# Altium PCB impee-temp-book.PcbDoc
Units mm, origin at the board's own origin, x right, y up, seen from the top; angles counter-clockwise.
Board outline 63.5 x 86.36 mm, 2 copper layers (Top Layer, Bottom Layer); 35 components, 21 nets, 124 pads, 134 vias.
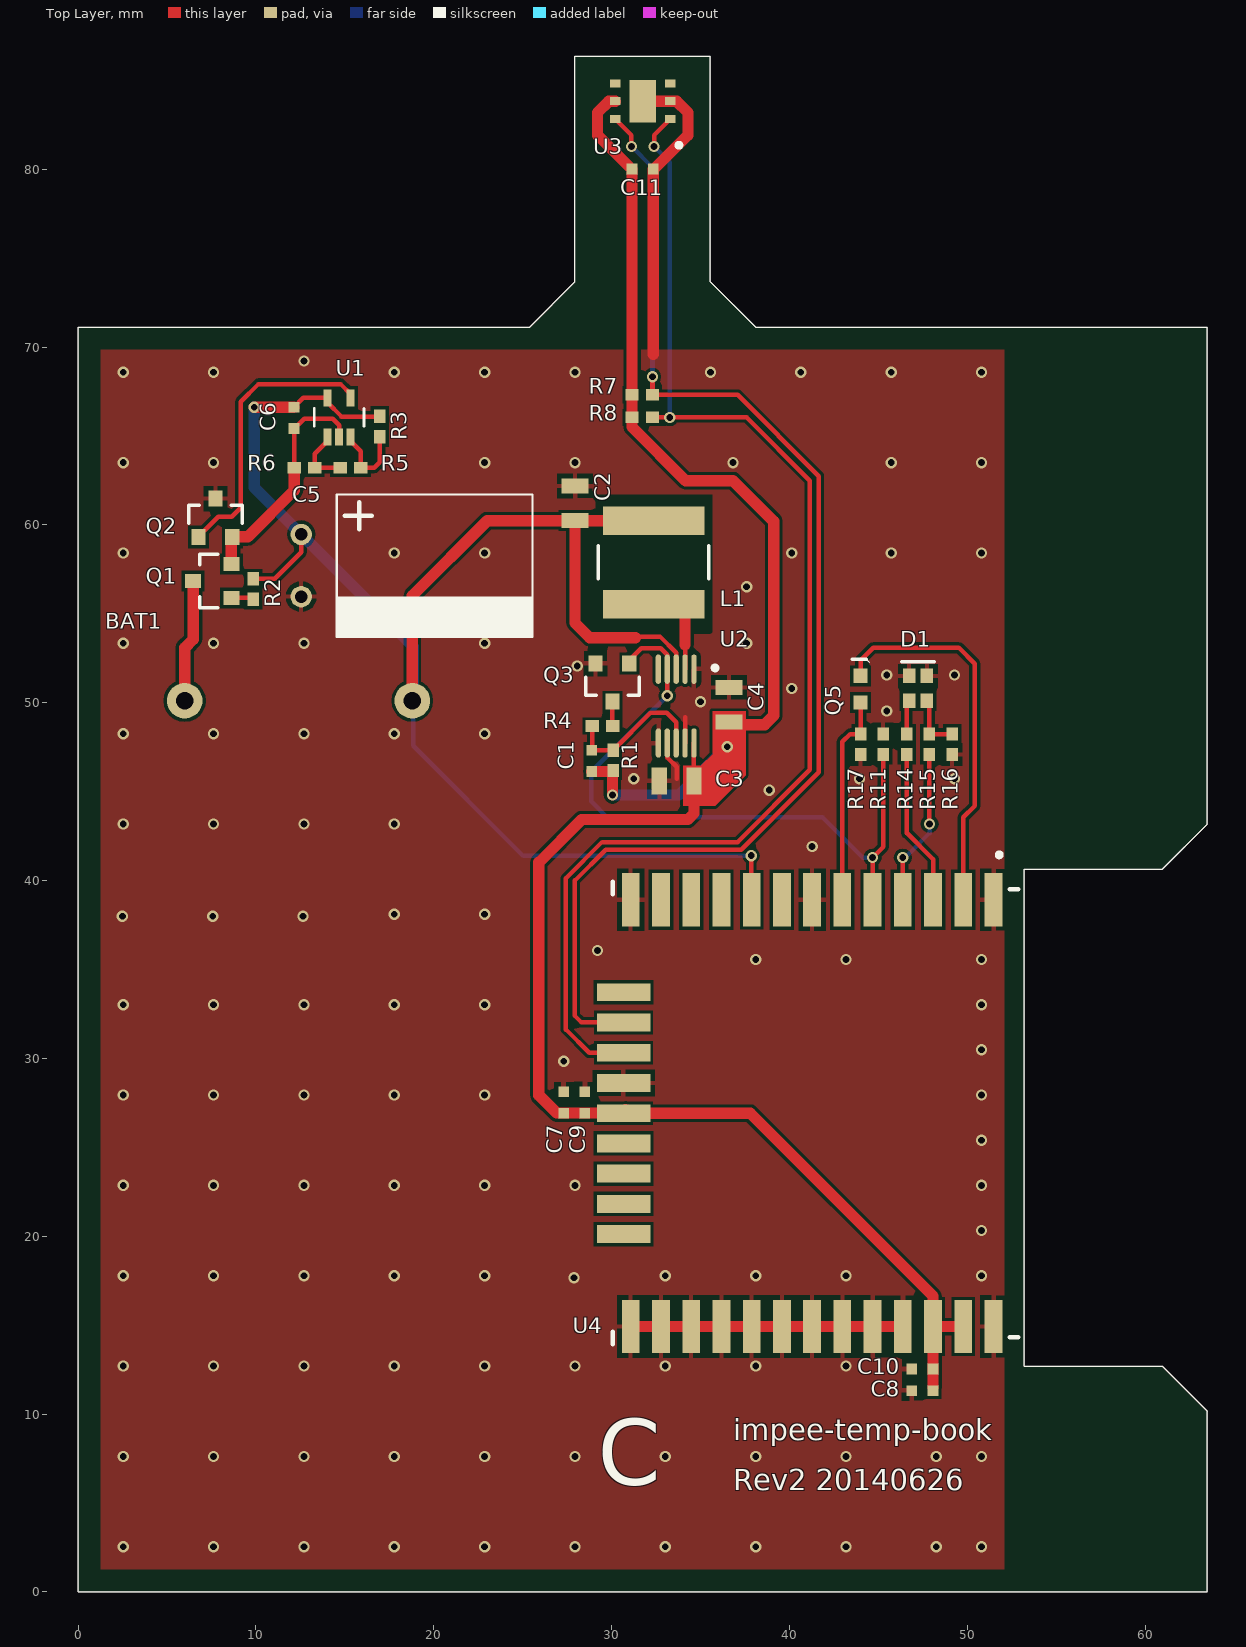
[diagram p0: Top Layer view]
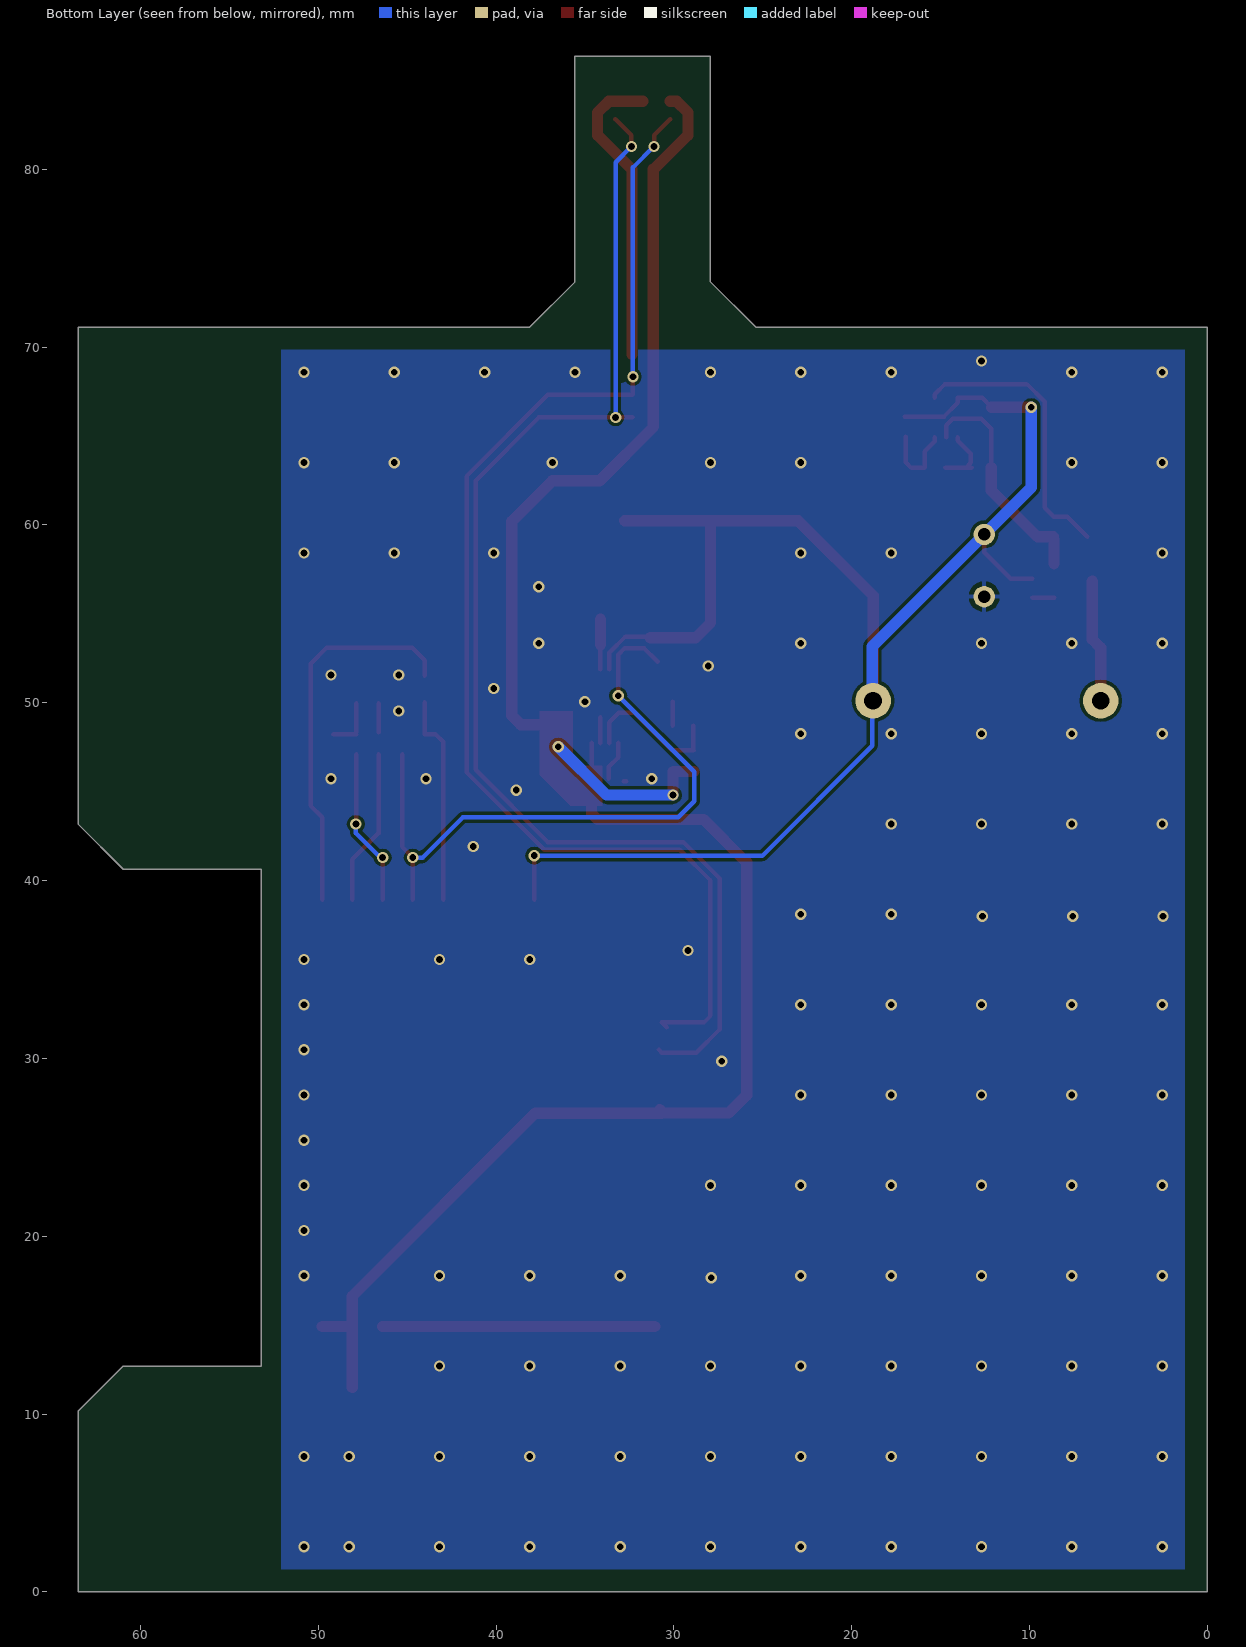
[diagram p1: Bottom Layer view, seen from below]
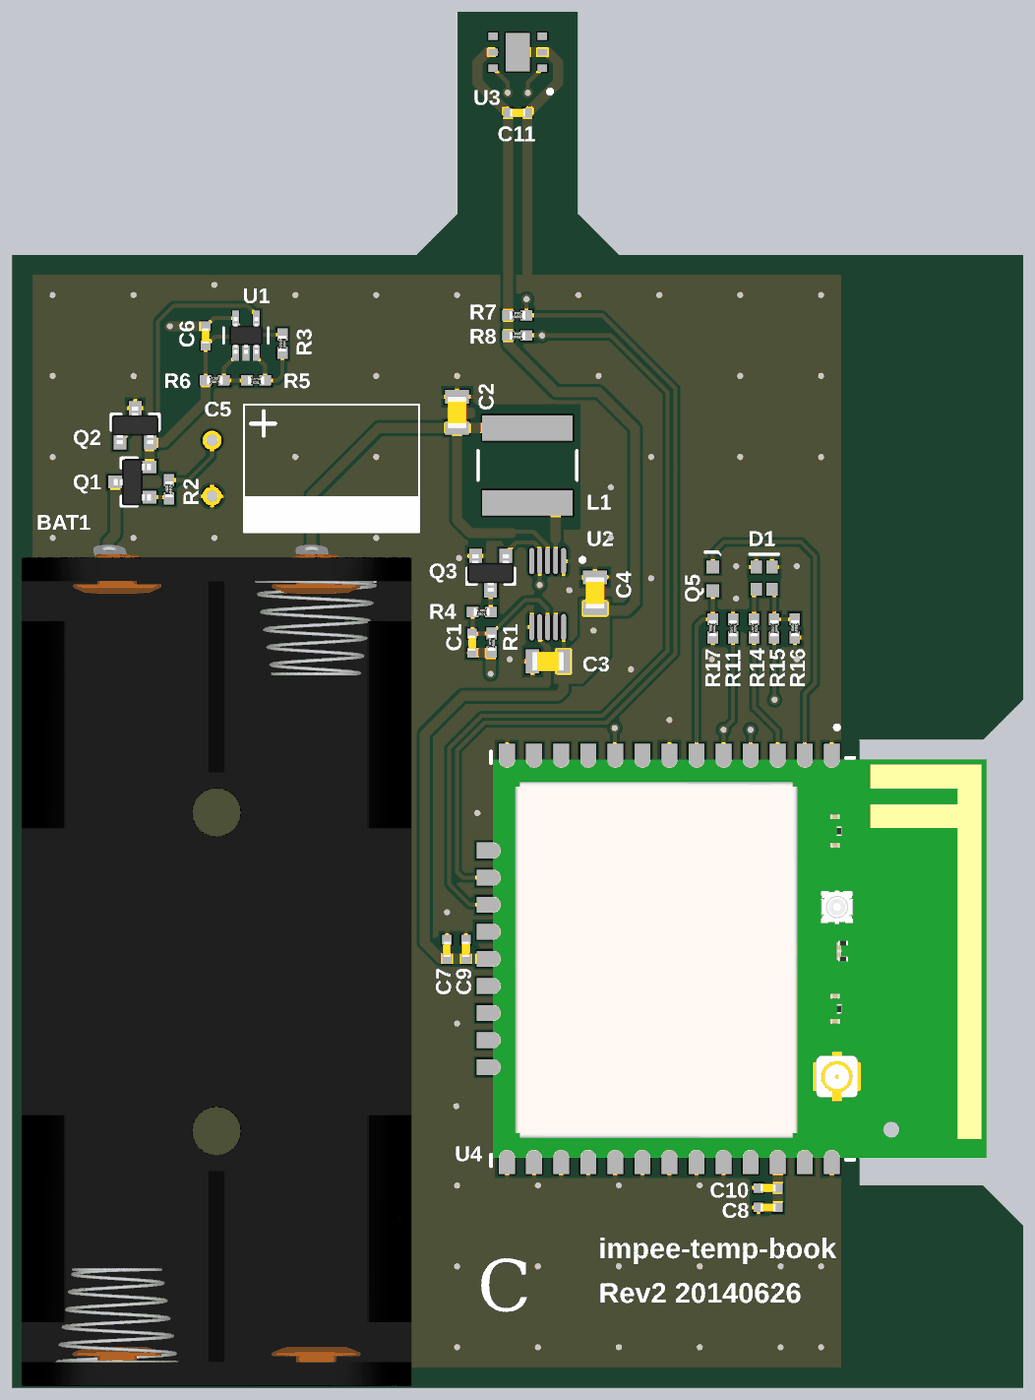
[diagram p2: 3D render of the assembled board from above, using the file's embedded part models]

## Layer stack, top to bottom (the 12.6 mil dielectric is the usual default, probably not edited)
Top Solder: solder mask 0.0102, Solder Resist, Dk 3.5
Top Layer: signal copper 0.0356
Dielectric 1: dielectric 0.32, FR-4, Dk 4.8
Bottom Layer: signal copper 0.0356
Bottom Solder: solder mask 0.0102, Solder Resist, Dk 3.5

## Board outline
0,71.12 25.4,71.12 27.94,73.66 27.94,86.36 35.56,86.36 35.56,73.66 38.1,71.12 63.5,71.12 63.5,43.18 60.96,40.64 53.213,40.64 53.213,12.7 60.96,12.7 63.5,10.16 63.5,0 0,0

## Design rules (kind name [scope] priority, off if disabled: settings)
Clearance [All] p1: gap=0.178
MinimumSolderMaskSliver [All] p1: minsoldermaskwidth=0.076
PolygonConnect ViaConnect [IsVia] p1: connectstyle=Direct reliefconductorwidth=0.254 reliefentries=4 polygonreliefangle="90 Angle" airgapwidth=0.254
PolygonConnect [All] p2: connectstyle=Relief reliefconductorwidth=0.254 reliefentries=4 polygonreliefangle="90 Angle" airgapwidth=0.254
RoutingVias [All] p1: holewidth=0.381 width=0.635 viastyle="Through Hole" minholewidth=0.381 minwidth=0.635 maxholewidth=0.711 maxwidth=1.27
SolderMaskExpansion [All] p1: expansion=0.102
UnpouredPolygon [All] p1: allowunpoured=FALSE
Width [All] p1: maxlimit=0.635 minlimit=0.254 preferedwidth=0.254
28 further rules are at their usual default settings.

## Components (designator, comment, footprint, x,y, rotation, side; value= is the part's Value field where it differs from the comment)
BAT1 "BATTERY" 12BH423-GR 12.395,26.111 r90 top
C1 "Ceramic Capacitor" CAPC1005X07N 28.88,46.736 r270 top
C2 "Ceramic Capacitor" CAPC2012X14N 27.94,61.214 r270 top
C3 "Ceramic Capacitor" CAPC2012X14N 33.655,45.593 r0 top
C4 "Ceramic Capacitor" CAPC2012X14N 36.601,49.886 r270 top
C5 "Polarized Capacitor" CAPAE80X110-RADIAL-RIGHTANGLE 12.548,59.461 r270 top
C6 "Ceramic Capacitor" CAPC1005X07N 12.141,66.015 r90 top
C7 "Ceramic Capacitor" CAPC1005X07N 27.305,27.521 r270 top
C8 "Ceramic Capacitor" CAPC1005X07N 47.475,11.318 r0 top
C9 "Ceramic Capacitor" CAPC1005X07N 28.499,27.521 r270 top
C10 "Ceramic Capacitor" CAPC1005X07N 47.475,12.537 r0 top
C11 "Ceramic Capacitor" CAPC1005X07N 31.75,80.01 r180 top
D1 "LED Red and Green" LED1616X07N-REDGREEN 47.227,50.814 r270 top
L1 "Inductor" INDP6060X28N 32.36,57.887 r270 top
Q1 "N-Channel MOSFET" SOT95P300X130-3N 7.544,56.845 r180 top
Q2 "N-Channel MOSFET" SOT95P300X130-3N 7.722,60.401 r90 top
Q3 "N-Channel MOSFET" SOT95P300X130-3N 30.048,51.13 r270 top
Q5 "PHOTOTRANSISTOR" PHOTOTRANS1608X8 44.001,50.764 r270 top
R1 "Resistor" RESC1005X04N 30.099,46.761 r270 top
R2 "Resistor" RESC1005X04N 9.855,56.388 r90 top
R3 "Resistor" RESC1005X04N 16.967,65.532 r270 top
R4 "Resistor" RESC1005X04N 29.489,48.692 r180 top
R5 "Resistor" RESC1005X04N 15.316,63.221 r180 top
R6 "Resistor" RESC1005X04N 12.725,63.221 r0 top
R7 "Resistor" RESC1005X04N 31.725,67.31 r0 top
R8 "Resistor" RESC1005X04N 31.725,66.04 r0 top
R11 "Resistor" RESC1005X04N 45.271,47.665 r270 top
R14 "Resistor" RESC1005X04N 46.592,47.665 r270 top
R15 "Resistor" RESC1005X04N 47.862,47.665 r270 top
R16 "Resistor" RESC1005X04N 49.149,47.665 r90 top
R17 "Resistor" RESC1005X04N 44.001,47.665 r90 top
U1 "MIC841" SOT65P200X125-5N 14.681,66.04 r90 top
U2 "XC9128" MSOP50P490X116-10N 33.63,49.809 r270 top
U3 "SI7021" Si7021 31.75,83.82 r180 top
U4 "imp module" IMP_MODULE 30.175,39.421 r270 top locked

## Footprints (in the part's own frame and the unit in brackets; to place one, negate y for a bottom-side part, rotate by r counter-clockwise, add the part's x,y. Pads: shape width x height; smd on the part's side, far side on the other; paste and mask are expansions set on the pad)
12BH423-GR [mm] "2xAAA Battery Holder PCB Through Hole"
  round 2 hole 1: +(24,-6.4) -(24,6.4)
  body extent -26.01,-12.69 26.79,11.81, height 13.18
CAPAE80X110-RADIAL-RIGHTANGLE [mm] "Cap, Polarized, Radial, 8mm Diameter, 11mm Hieght, Right Angle"
  round 1.2 hole 0.7: 1(0,0) 2(3.5,0)
  silkscreen extent -2.25,2 5.75,13, body extent -2.22,-0.25 5.75,13, height 7.99
CAPC1005X07N [mm] "Chip Capacitor, 2-Leads, Body 1.0x0.5mm, IPC Medium Density"
  rect 0.6x0.6 smd: 1(-0.6,0) 2(0.6,0)
  body extent -0.5,-0.25 0.5,0.25, height 0.6
CAPC2012X14N [mm] "Chip Capacitor, 2-Leads, Body 2.0x1.3mm, IPC Medium Density"
  rect 0.85x1.5 smd: 1(-0.975,0) 2(0.975,0)
  body extent -1,-0.6 1,0.6, height 1.4
IMP_MODULE [mm] "Imp Module, Shadow and Chase"
  rect 3x1 smd: 1(0.5,21.3) 2(0.5,19.6) 3(0.5,17.9) 4(0.5,16.2) 5(0.5,14.5) 6(0.5,12.8) 7(0.5,11.1) 8(0.5,9.4) 9(0.5,7.7) 10(0.5,6) 11(0.5,4.3) 12(0.5,2.6) 13(0.5,0.9) 23(24.5,0.9) 24(24.5,2.6) 25(24.5,4.3) 26(24.5,6) 27(24.5,7.7) 28(24.5,9.4) 29(24.5,11.1) 30(24.5,12.8) 31(24.5,14.5) 32(24.5,16.2) 33(24.5,17.9) 34(24.5,19.6) 35(24.5,21.3)
  rect 1x3 smd: 14(5.7,0.5) 15(7.4,0.5) 16(9.1,0.5) 17(10.8,0.5) 18(12.5,0.5) 19(14.2,0.5) 20(15.9,0.5) 21(17.6,0.5) 22(19.3,0.5)
  silkscreen extent -2.15,-0.1 25.5,22.7, body extent 0,0 25,31, height 1.7
INDP6060X28N [mm] "Precision Wire Wound Inductor, 2-Leads, Body 6.0x6.0mm, IPC Medium Density"
  rect 1.6x5.7 smd: 1(-2.35,0) 2(2.35,0)
  silkscreen extent -0.92,-3.1 0.92,3.1, body extent -3.1,-3.1 3.1,3.1, height 2.8
LED1616X07N-REDGREEN [mm] "Bi-Color LED, 0606 (1616 metric), Red, Green"
  rect 0.8x0.7 smd: AG(0.7,-0.5) AR(0.7,0.5) KG(-0.7,-0.5) KR(-0.7,0.5)
  silkscreen extent -1.5,-0.9 -1.5,0.9, body extent -0.8,-0.8 0.8,0.8, height 0.7
MSOP50P490X116-10N [mm] "MSOP, 10-Leads, Body 3.1x3.1mm (max), Pitch 0.50mm, IPC Medium Density"
  oval 1.65x0.3 smd: 1(-2.075,1) 2(-2.075,0.5) 3(-2.075,0) 4(-2.075,-0.5) 5(-2.075,-1) 6(2.075,-1) 7(2.075,-0.5) 8(2.075,0) 9(2.075,0.5) 10(2.075,1)
  silkscreen extent -2.27,2.06 -2.02,2.31, body extent -1.55,-1.55 1.55,1.55, height 1.16
PHOTOTRANS1608X8 [mm] "Phototransistor, Top View, 0603 (1608 Metric)"
  rect 0.8x0.8 smd: C(-0.75,0) E(0.75,0)
  silkscreen extent -1.68,-0.47 -1.5,0.5, body extent -0.8,-0.4 0.8,0.4, height 0.8
RESC1005X04N [mm] "Chip Resistor, 2-Leads, Body 1.0x0.5mm, IPC Medium Density"
  rect 0.75x0.65 smd: 1(-0.575,0) 2(0.575,0)
  body extent -0.5,-0.25 0.5,0.25, height 0.35
Si7021 [mm] "DFN, 7-Leads, Body 3x3mm, 1mm Pitch, IPC Medium Density"
  rect 0.6x0.45 smd: 1(-1.55,1) 2(-1.55,0) 3(-1.55,-1) 4(1.55,-1) 5(1.55,0) 6(1.55,1)
  rect 1.5x2.4 smd: 7(0,0)
  silkscreen extent -2.16,2.35 -1.91,2.6, body extent -1.55,-1.55 1.55,1.55, height 0.75
SOT65P200X125-5N [mm] "SOT-323-5, SC70-5"
  rect 0.95x0.45 smd paste+0 mask+0.05: 1(-1.1,0.65) 2(-1.1,0) 3(-1.1,-0.65) 4(1.1,-0.65) 5(1.1,0.65)
  silkscreen extent -0.5,-1.4 0.5,1.4, body extent -1.15,-1.05 1.15,1.05, height 1
SOT95P300X130-3N [mm] "SOT-23"
  rect 0.9x0.8 smd: 1(-1.075,0.95) 2(-1.075,-0.95) 3(1.075,0)
  silkscreen extent -0.3,-1.5 0.7,1.5, body extent -1.17,-1.45 1.17,1.47, height 1

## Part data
BAT1: library part BAT00002, "2xAAA Series Battery Holder with Through-Hole PCB Mount"
C1: library part CAPC00041, "CAP,C0G,12pF,5%,50V,0402#"
C2 C3: library part CAPC00039, "CAP,X5R,22uF,10%,6.3V,0805,#"
C4: library part CAPC00036, "CAP,X5R,10uF,10%,6.3V,0805,#"
C5: library part CAPC00052, "CAP,ALUM,1000uF,20%,6.3V, 8mm DIA,RADIAL#"
C6 C11: library part CAPC00002, "CAP,X5R,0.1uF,10%,6.3V, 0402,#"
C7 C8: library part CAPC00005, "CAP,X5R,1.0uF,10%,6.3V, 0402,#"
C9 C10: library part CAPC00043, "CAP,C0G,100pF,5%,50V,0402"
D1: library part LED00012, "LED, Red and Green, 2/2V, 631/571nm, 25/35mcd, SMT"
L1: library part IND00007, "IND, 4.7uH, 20%, 2.7A Isat, 403 mOhm, 6028"
Q1 Q2: library part NFET00004, "NFET, 20V, 4.2A, SOT23"
Q3: library part NFET00003, "NFET, 25V, 220mA, SOT23"
Q5: library part PHOTO00011, "Phototrans, Clear, Top View, 940nm, 0.4V, 0.6mA, 0603"
R1: library part RES00040, "RES,270K,1%,0.063W,0402"
R2 R11: library part RES00001, "RES,100k,5%,0.063W,0402,#"
R3: library part RES00009, "RES,470k,5%,0.063W,0402"
R4: library part RES00041, "RES,43K,1%,0.063W,0402"
R5: library part RES00015, "RES,270K,5%,0.063W,0402"
R6: library part RES00010, "RES,1M,5%,0.063W,0402,#"
R7 R8: library part RES00038, "RES,4.7K,1%,0.1W,0402,#"
R14 R15: library part RES00024, "RES,100 Ohm,1%,0.063W,0402,#"
R16: library part RES00006, "RES,10k,5%,0.063W,0402,#"
R17: library part RES00008, "RES,47k,5%,0.063W,0402"
U1: library part IC00032, "IC, Comparator with Reference and Programmable Hysteresis, SOT-353"
U2: library part IC00026, "IC, DC/DC boost,Adj Output,6Vin,500mA,MSOP10"
U3: library part IC00157, "IC, Sensor, Temp+Humidity, Si7021, DFN6"
U4: library part MOD00002, "Module, Electric Imp Solder Down with Antenna"

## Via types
v1: diameter 0.635, hole 0.381, Top Layer to Bottom Layer, tented both sides, 134 vias

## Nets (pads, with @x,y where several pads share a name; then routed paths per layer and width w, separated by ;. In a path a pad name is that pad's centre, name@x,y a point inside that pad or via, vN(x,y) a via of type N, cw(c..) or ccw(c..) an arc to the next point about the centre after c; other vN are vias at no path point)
3V0_EN: Q3.1 R11.2 U2.4 U4.5 | length 38.1
  Top Layer w0.254: Q3.1@30.909,52.294 31.676,53.061 32.772,53.061 33.13,52.703 U2.4 v1(33.13,50.386) ; U4.5 v1@44.675,41.139 ; v1(44.675,41.295) 45.271,41.891 R11.2
  Bottom Layer w0.254: v1(33.13,50.386) 28.854,46.11 28.854,44.45 29.743,43.561 41.859,43.561 44.125,41.295 v1(44.675,41.295)
BAT+: BAT1.+ C2.2 C5.1 C6.2 L1.1 R2.2 R3.1 U1.5 U2.3 U4.9 | length 93.8
  Top Layer w0.254: R2.2 11.053,56.963 12.548,58.458 C5.1 ; C6.2 12.667,67.14 U1.5 14.031,66.868 14.808,66.091 R3.1@17.018,66.091 ; 31.344,53.645 31.42,53.721 32.722,53.721 33.63,52.813 U2.3 ; U4.9@37.846,38.93 v1(37.846,41.402)
  Top Layer w0.635: v1(9.906,66.615) C6.2 ; BAT1.+@18.795,50.035 18.795,56.019 23.01,60.233 L1.1@32.766,60.233 ; C2.2 27.94,54.483 28.778,53.645 31.344,53.645
  Bottom Layer w0.254: BAT1.+@18.847,50.163 18.847,47.574 25.019,41.402 v1(37.846,41.402)
  Bottom Layer w0.635: v1(9.906,66.615) 9.906,62.103 C5.1 18.847,53.162 BAT1.+@18.847,50.163
BAT-: BAT1.- Q1.3 | length 7
  Top Layer w0.635: BAT1.-@5.995,50.035 5.995,53.086 6.469,53.56 Q1.3
FB: C1.1 R1.1 R4.2 U2.8 | length 8.4
  Top Layer w0.254: R4.2 28.914,47.371 C1.1 R1.1 ; R1.1 32.191,49.428 33.096,49.428 33.63,48.895 U2.8
GND: C2.1 C3.1 C4.1 C5.2 C7.1 C8.1 C9.1 C10.1 C11.1 D1.KG D1.KR Q2.3 Q3.2 R11.1 R16.1 R17.1 U2.1 U2.6 U2.7 U2.9 U3.2 U3.7 U4.1 U4.7 U4.13 U4.17 U4.23 U4.24 U4.25 U4.26 U4.27 U4.28 U4.29 U4.30 U4.31 U4.32 U4.35 | length 36.3
  Top Layer w0.254: C3.1 C3.1@32.806,45.593 ; U2.7 33.13,46.916 33.655,46.391 33.655,45.72 ; U2.9 34.13,49.182
  Top Layer w0.635: U4.23 U4.24 U4.25 U4.26 U4.27 U4.28 U4.29 U4.30 U4.31 U4.32 ; U3.7 U3.2 33.655,83.82 34.29,83.185 34.29,81.915 C11.1@32.385,80.01 ; 32.35,69.596 C11.1
  other v1: 2.54,2.54 7.62,2.54 12.7,2.54 17.78,2.54 22.86,2.54 27.94,2.54 33.02,2.54 38.1,2.54 43.18,2.54 48.26,2.54 50.8,2.54 2.54,7.62 7.62,7.62 12.7,7.62 17.78,7.62 22.86,7.62 27.94,7.62 33.02,7.62 38.1,7.62 43.18,7.62 48.26,7.62 50.8,7.62 2.54,12.7 7.62,12.7 12.7,12.7 17.78,12.7 22.86,12.7 27.94,12.7 33.02,12.7 38.1,12.7 43.18,12.7 27.891,17.668 2.54,17.78 7.62,17.78 12.7,17.78 17.78,17.78 22.86,17.78 33.02,17.78 38.1,17.78 43.18,17.78 50.8,17.78 50.8,20.32 2.54,22.86 7.62,22.86 12.7,22.86 17.78,22.86 22.86,22.86 27.94,22.86 50.8,22.86 50.8,25.4 2.54,27.94 7.62,27.94 12.7,27.94 17.78,27.94 22.86,27.94 50.8,27.94 27.305,29.845 50.8,30.48 2.54,33.02 7.62,33.02 12.7,33.02 17.78,33.02 22.86,33.02 50.8,33.02 38.1,35.56 43.18,35.56 50.8,35.56 29.21,36.068 2.491,37.988 7.571,37.988 12.651,37.988 17.78,38.1 22.86,38.1 41.275,41.91 2.54,43.18 7.62,43.18 12.7,43.18 17.78,43.18 38.862,45.085 31.242,45.72 43.942,45.72 49.276,45.72 2.54,48.26 7.62,48.26 12.7,48.26 17.78,48.26 22.86,48.26 45.466,49.53 35.003,50.053 40.132,50.8 45.466,51.562 49.276,51.562 28.067,52.07 2.54,53.34 7.62,53.34 12.7,53.34 22.86,53.34 37.592,53.34 37.592,56.515 2.54,58.42 17.78,58.42 22.86,58.42 40.132,58.42 45.72,58.42 50.8,58.42 2.54,63.5 7.62,63.5 22.86,63.5 27.94,63.5 36.83,63.5 45.72,63.5 50.8,63.5 2.54,68.58 7.62,68.58 17.78,68.58 22.86,68.58 27.94,68.58 35.56,68.58 40.64,68.58 45.72,68.58 50.8,68.58 12.7,69.215
LED_GREEN: R14.2 U4.3 | length 8.8
  Top Layer w0.254: R14.2 46.592,42.655 46.626,42.655 48.075,41.206 U4.3
LED_RED: R15.2 U4.4 | length 8.9
  Top Layer w0.254: U4.4 v1(46.375,41.295) ; R15.2 47.862,43.197 v1(47.879,43.18)
  Bottom Layer w0.254: v1(46.375,41.295) 46.502,41.295 47.879,42.672 v1(47.879,43.18)
LX: L1.2 U2.2 | length 2.8
  Top Layer w0.254: U2.2 34.13,53.246
  Top Layer w0.635: 34.13,53.246 34.13,54.694
NetC6_1: C6.1 Q1.2 Q2.2 R6.1 U1.2 | length 13.1
  Top Layer w0.254: Q2.2@8.54,59.174 Q2.2@8.621,59.174 ; C6.1 C6.1@12.15,65.405 ; R6.1 C6.1@12.15,65.405 ; U1.2 14.681,65.6 14.317,65.964 12.709,65.964 C6.1@12.15,65.405
  Top Layer w0.635: Q1.2 Q2.2@8.619,59.172 ; Q2.2 9.542,59.326 12.15,61.934 R6.1
NetD1_AG: D1.AG R14.1 | length 1.6
  Top Layer w0.254: R14.1@46.592,48.341 D1.AG@46.592,49.979
NetD1_AR: D1.AR R15.1 R16.2 | length 2.9
  Top Layer w0.254: R15.1 R16.2 ; R15.1@47.862,48.341 D1.AR@47.862,49.979
NetQ1_1: Q1.1 R2.1 | length 1.2
  Top Layer w0.254: Q1.1 R2.1@9.836,55.895
NetQ2_1: Q2.1 U1.4 | length 16.1
  Top Layer w0.254: Q2.1@6.76,59.338 7.874,60.452 8.636,60.452 9.144,60.96 9.144,66.92 10.144,67.92 14.757,67.92 15.331,67.346 U1.4
NetQ3_3: Q3.3 R4.1 | length 1.3
  Top Layer w0.254: R4.1@30.048,48.708 Q3.3
NetR3_2: R3.2 R5.1 U1.3 | length 4.6
  Top Layer w0.254: U1.3 15.331,64.704 15.891,64.144 R5.1 16.662,63.221 16.967,63.525 R3.2
NetR5_2: R5.2 R6.2 U1.1 | length 3.6
  Top Layer w0.254: R6.2@13.259,63.221 R5.2 ; R6.2@13.564,63.221 13.3,63.484 13.3,63.999 14.031,64.73 U1.1
OPTO_BIAS: Q5.C U4.2 | length 21.5
  Top Layer w0.254: Q5.C 44.001,52.383 44.704,53.086 49.53,53.086 50.419,52.197 50.419,44.196 49.775,43.552 U4.2
OPTO_IN: Q5.E R17.2 U4.6 | length 11.9
  Top Layer w0.254: U4.6 42.975,47.801 43.414,48.24 R17.2 Q5.E
SCL: R7.2 U3.6 U4.15 | length 71.4
  Top Layer w0.254: U3.6 30.21,82.82 31.115,81.915 v1(31.115,81.28) ; U4.15@30.404,31.75 U4.15 28.304,32.021 27.94,32.385 27.94,40.005 29.667,41.732 37.296,41.732 41.656,46.092 41.656,62.738 37.084,67.31 R7.2 v1(32.3,68.326)
  Bottom Layer w0.254: v1(31.115,81.28) 32.3,80.095 v1(32.3,68.326)
SDA: R8.2 U3.1 U4.16 | length 72.8
  Top Layer w0.254: U4.16@30.834,30.48 U4.16 28.734,30.321 27.432,31.623 27.432,40.132 29.464,42.164 37.084,42.164 41.148,46.228 41.148,62.484 37.592,66.04 v1(33.274,66.04) R8.2@32.325,66.04 ; v1(32.385,81.28) 32.385,81.915 33.29,82.82 U3.1
  Bottom Layer w0.254: v1(32.385,81.28) 33.274,80.391 v1(33.274,66.04)
VBAT/3V0: C1.2 C3.2 C4.2 C7.2 C8.2 C9.2 C10.2 C11.2 R1.2 R7.1 R8.1 U2.10 U3.5 U4.18 U4.33 U4.34 | length 113.4
  Top Layer w0.254: C3.2@34.63,45.734 U2.10
  Top Layer w0.635: C1.2 30.049,46.136 v1(30.049,44.806) ; U3.5 29.845,83.82 29.21,83.185 29.21,81.915 C11.2@31.115,80.01 ; U4.18 37.79,26.921 48.075,16.635 C8.2@48.075,11.495 ; U4.18@30.79,27.111 30.602,26.924 26.913,26.924 25.908,27.929 25.908,41.021 28.321,43.434 34.29,43.434 34.63,43.774 C3.2 ; C11.2 R7.1 R8.1 31.15,65.499 34.165,62.484 36.83,62.484 39.116,60.198 39.116,49.276 38.608,48.768 C4.2@37.265,48.768 ; U4.33@48.253,14.921 U4.34
  Bottom Layer w0.635: v1(30.049,44.806) 33.782,44.806 v1(36.5,47.523)
pads on no net: U2.5 U3.3 U3.4 U4.8 U4.10 U4.11 U4.12 U4.14 U4.19 U4.20 U4.21 U4.22

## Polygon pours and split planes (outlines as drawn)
GND on Bottom Layer "Bottom Layer-gnd" (solid, remove dead copper, pour order 4): 1.27,69.85 52.07,69.85 52.07,41.91 52.07,11.43 52.07,1.27 26.67,1.27 1.27,1.27
GND on Top Layer "Top Layer-gnd" (solid, remove dead copper, pour order 3): 1.27,69.85 52.07,69.85 52.07,41.91 52.07,11.43 52.07,1.27 26.67,1.27 1.27,1.27

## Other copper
Top Layer:
  region net VBAT/3V0: 35.674,49.513 35.674,47.104 35.015,46.445 34.027,46.445 34.027,44.205 34.036,44.196 35.814,44.196 37.529,45.911 37.529,49.513
  pour cut-out: 29.083,61.722 35.687,61.722 35.687,53.975 35.56,53.848 29.083,53.848

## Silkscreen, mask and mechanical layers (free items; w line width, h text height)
Top Overlay:
  the board outline again, w0.025
  text "impee-temp-book" at 36.83,8.128 h2.03
  text "Rev2 20140626" at 36.83,5.334 h2.03
  text "C" at 29.21,4.826 h6.35
Mechanical 2:
  the board outline again, w0.025
Drill Drawing:
  circle w0.025: c74.501,9.398 r0.635
  lines w0.025: 73.866,6.223 75.136,6.223 74.501,4.953 73.866,6.223 ; 73.866,12.573 75.136,12.573 75.136,13.843 73.866,13.843 73.866,12.573
  lines w0.381: 72.136,3.81 170.662,3.81 ; 72.136,15.24 170.662,15.24 ; 86.128,0 86.128,19.05 ; 103.853,0 103.853,19.05 ; 138.031,0 138.031,19.05 ; 150.88,0 150.88,19.05 ; 72.136,0 170.662,0 170.662,19.05 72.136,19.05 72.136,0
  text "Symbol" at 74.422,16.383 h1.83
  text "Hit Count" at 87.271,16.383 h1.83
  text "Finished Hole Size" at 104.996,16.383 h1.83
  text "Plated" at 139.174,16.383 h1.83
  text "Hole Type" at 152.023,16.383 h1.83
  text "2" at 87.271,12.573 h1.52
  text "27.56mil (0.700mm)" at 104.996,12.573 h1.52
  text "PTH" at 139.174,12.573 h1.52
  text "Round" at 152.023,12.573 h1.52
  text "2" at 87.271,8.763 h1.52
  text "39.37mil (1.000mm)" at 104.996,8.763 h1.52
  text "PTH" at 139.174,8.763 h1.52
  text "Round" at 152.023,8.763 h1.52
  text "134" at 87.271,4.953 h1.52
  text "15.00mil (0.381mm)" at 104.996,4.953 h1.52
  text "PTH" at 139.174,4.953 h1.52
  text "Round" at 152.023,4.953 h1.52
  text "138 Total" at 87.271,1.143 h1.52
